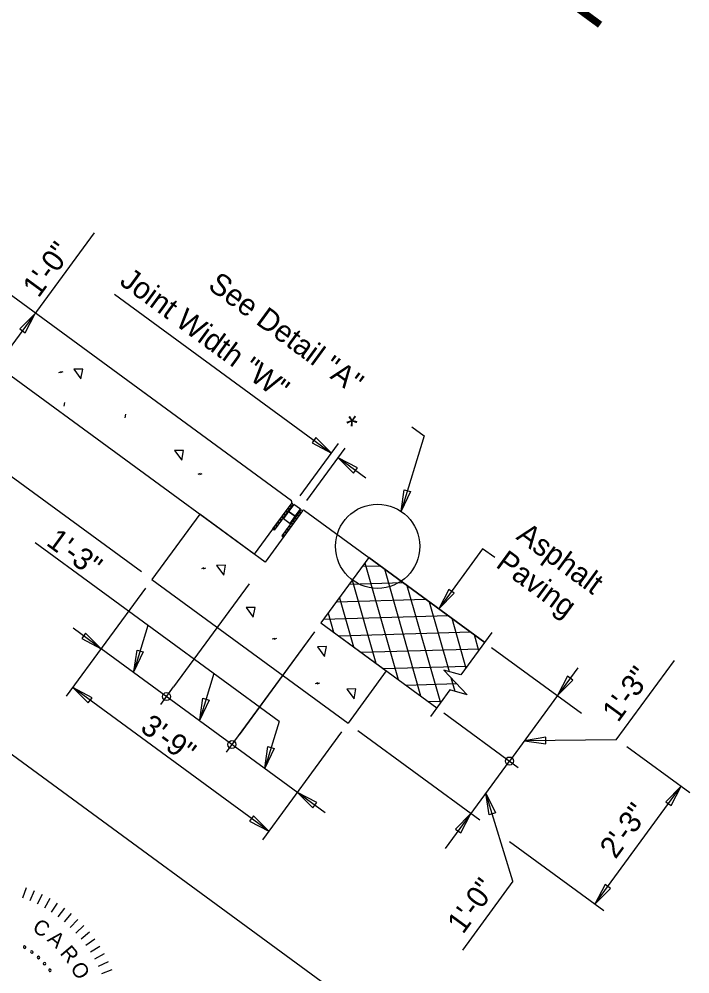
# Model space of a CAD drawing. Extents: x 1970731 to 1970899, y 796145 to 796301.
# Drawn here: x 1970821.64 to 1970837.15, y 796175.27 to 796197.36 of the extents above; entities that cross this region are included whole.
import ezdxf

# ---------------------------------------------------------------- set-up
doc = ezdxf.new("R2010")
doc.units = 0
for name, color, linetype in [('BR_AUTO DIMENSION', 7, 'Continuous'), ('BR_BORDER LINES', 7, 'Continuous'), ('BR_CONCRETE', 7, 'Continuous'), ('BR_DETAILS', 7, 'Continuous'), ('BR_STRUCTURAL STEEL', 7, 'Continuous'), ('BR_TABLE LINES', 7, 'Continuous'), ('BR_TEXT', 7, 'Continuous')]:
    doc.layers.add(name, color=color, linetype=linetype)

msp = doc.modelspace()

# ---------------------------------------------------------------- linework, layer by layer
at = {"layer": 'BR_AUTO DIMENSION'}
for p, q in [((1970818.787, 796186.151), (1970823.376, 796192.419)), ((1970823.84, 796191.001), (1970828.862, 796187.324)), ((1970824.464, 796184.573), (1970819.679, 796188.077)), ((1970830.722, 796187.929), (1970831.002, 796187.723)), ((1970831.002, 796187.723), (1970830.47, 796185.975)), ((1970828.139, 796186.336), (1970829.025, 796187.547)), ((1970828.29, 796186.225), (1970829.176, 796187.436)), ((1970829.658, 796186.74), (1970829.013, 796187.213)), ((1970827.648, 796181.116), (1970822.009, 796185.245)), ((1970832.358, 796185.11), (1970831.341, 796183.721)), ((1970832.639, 796184.904), (1970832.358, 796185.11)), ((1970824.557, 796184.195), (1970822.728, 796181.698)), ((1970826.956, 796184.298), (1970825.21, 796181.913)), ((1970823.533, 796182.797), (1970822.888, 796183.27)), ((1970824.615, 796183.337), (1970824.289, 796182.267)), ((1970828.469, 796183.19), (1970826.428, 796180.402)), ((1970828.469, 796183.19), (1970826.723, 796180.805)), ((1970828.717, 796179.001), (1970823.537, 796182.794)), ((1970832.565, 796182.826), (1970834.645, 796181.303)), ((1970834.559, 796182.358), (1970834.086, 796181.712)), ((1970835.45, 796180.686), (1970836.793, 796182.521)), ((1970826.14, 796182.221), (1970825.814, 796181.15)), ((1970827.415, 796178.576), (1970822.876, 796181.899)), ((1970824.915, 796181.51), (1970825.21, 796181.913)), ((1970834.086, 796181.712), (1970832.978, 796180.199)), ((1970831.457, 796181.313), (1970833.18, 796180.051)), ((1970827.648, 796181.116), (1970827.318, 796180.031)), ((1970829.096, 796180.873), (1970827.267, 796178.375)), ((1970829.474, 796180.906), (1970832.294, 796178.841)), ((1970835.45, 796180.686), (1970833.323, 796180.669)), ((1970835.696, 796180.533), (1970837.152, 796179.467)), ((1970831.496, 796178.174), (1970832.978, 796180.199)), ((1970834.957, 796176.891), (1970836.951, 796179.614)), ((1970833.059, 796177.422), (1970832.433, 796179.454)), ((1970832.979, 796178.34), (1970835.159, 796176.744)), ((1970833.059, 796177.422), (1970831.891, 796175.826))]:
    msp.add_line(p, q, dxfattribs=at)
for points in [[(1970821.775, 796190.106), (1970822.01, 796190.553), (1970821.654, 796190.194)], [(1970828.414, 796187.559), (1970828.862, 796187.324), (1970828.503, 796187.68)], [(1970829.461, 796186.978), (1970829.013, 796187.213), (1970829.372, 796186.857)], [(1970830.687, 796186.432), (1970830.47, 796185.975), (1970830.544, 796186.475)], [(1970831.576, 796184.169), (1970831.341, 796183.721), (1970831.697, 796184.08)], [(1970823.086, 796183.032), (1970823.533, 796182.797), (1970823.174, 796183.153)], [(1970824.506, 796182.723), (1970824.289, 796182.267), (1970824.363, 796182.767)], [(1970834.321, 796182.16), (1970834.086, 796181.712), (1970834.442, 796182.071)], [(1970823.324, 796181.664), (1970822.876, 796181.899), (1970823.235, 796181.543)], [(1970826.031, 796181.607), (1970825.814, 796181.15), (1970825.888, 796181.651)], [(1970833.822, 796180.748), (1970833.323, 796180.669), (1970833.823, 796180.598)], [(1970827.535, 796180.488), (1970827.318, 796180.031), (1970827.392, 796180.531)], [(1970828.52, 796179.239), (1970828.072, 796179.474), (1970828.431, 796179.118)], [(1970836.716, 796179.167), (1970836.951, 796179.614), (1970836.595, 796179.255)], [(1970832.509, 796178.955), (1970832.433, 796179.454), (1970832.652, 796178.999)], [(1970826.967, 796178.811), (1970827.415, 796178.576), (1970827.056, 796178.932)], [(1970831.854, 796178.535), (1970832.088, 796178.983), (1970831.732, 796178.624)], [(1970835.192, 796177.339), (1970834.957, 796176.891), (1970835.313, 796177.25)]]:
    msp.add_lwpolyline(points, close=True, dxfattribs=at)
for centre in [(1970825.046, 796181.689), (1970826.559, 796180.581), (1970832.978, 796180.199)]:
    msp.add_circle(centre, 0.0928, dxfattribs=at)
at = {"layer": 'BR_BORDER LINES'}
msp.add_line((1970811.99, 796187.287), (1970829.306, 796174.609), dxfattribs=at)
at = {"layer": 'BR_CONCRETE'}
for p, q in [((1970827.934, 796186.216), (1970803.754, 796203.919)), ((1970827.073, 796184.987), (1970802.867, 796202.709)), ((1970827.073, 796184.987), (1970802.867, 796202.709)), ((1970827.941, 796186.172), (1970827.073, 796184.987)), ((1970827.941, 796186.172), (1970827.073, 796184.987)), ((1970825.813, 796185.91), (1970824.705, 796184.397)), ((1970825.813, 796185.91), (1970824.705, 796184.397)), ((1970827.325, 796184.802), (1970825.813, 796185.91)), ((1970827.325, 796184.802), (1970825.813, 796185.91)), ((1970828.193, 796185.987), (1970827.325, 796184.802)), ((1970828.193, 796185.987), (1970827.325, 796184.802)), ((1970828.237, 796185.994), (1970829.724, 796184.905)), ((1970828.237, 796185.994), (1970829.724, 796184.905)), ((1970829.724, 796184.905), (1970828.617, 796183.392)), ((1970829.724, 796184.905), (1970828.617, 796183.392)), ((1970829.724, 796184.905), (1970828.617, 796183.392)), ((1970829.724, 796184.905), (1970828.617, 796183.392)), ((1970829.724, 796184.905), (1970832.405, 796182.942)), ((1970829.724, 796184.905), (1970832.405, 796182.942)), ((1970824.705, 796184.397), (1970829.244, 796181.074)), ((1970824.705, 796184.397), (1970829.244, 796181.074)), ((1970828.617, 796183.392), (1970830.13, 796182.285)), ((1970828.617, 796183.392), (1970830.13, 796182.285)), ((1970828.617, 796183.392), (1970830.13, 796182.285)), ((1970830.13, 796182.285), (1970829.244, 796181.074)), ((1970830.13, 796182.285), (1970829.244, 796181.074))]:
    msp.add_line(p, q, dxfattribs=at)
for centre, radius, start, end in [((1970827.916, 796186.191), 0.0313, 323.7906, 53.7906), ((1970828.218, 796185.969), 0.0312, 53.7906, 143.7906)]:
    msp.add_arc(centre, radius, start, end, dxfattribs=at)
at = {"layer": 'BR_DETAILS'}
for p, q in [((1970822.606, 796189.203), (1970822.55, 796189.182)), ((1970822.644, 796189.199), (1970822.588, 796189.178)), ((1970822.676, 796188.41), (1970822.694, 796188.491)), ((1970824.089, 796188.141), (1970824.106, 796188.221)), ((1970825.824, 796186.847), (1970825.768, 796186.826)), ((1970825.862, 796186.843), (1970825.806, 796186.822)), ((1970825.91, 796184.664), (1970825.854, 796184.644)), ((1970825.949, 796184.66), (1970825.892, 796184.639)), ((1970827.549, 796183.035), (1970827.492, 796183.014)), ((1970827.587, 796183.031), (1970827.531, 796183.01)), ((1970832.572, 796183.171), (1970831.856, 796182.193)), ((1970828.544, 796182.004), (1970828.487, 796181.984)), ((1970828.582, 796182), (1970828.525, 796181.979)), ((1970831.6, 796181.842), (1970831.15, 796181.228))]:
    msp.add_line(p, q, dxfattribs=at)
for points in [[(1970823.065, 796189.04), (1970823.107, 796189.266), (1970822.899, 796189.264), (1970823.065, 796189.04)], [(1970825.397, 796187.156), (1970825.439, 796187.383), (1970825.231, 796187.381), (1970825.397, 796187.156)], [(1970826.369, 796184.501), (1970826.412, 796184.728), (1970826.204, 796184.725), (1970826.369, 796184.501)], [(1970827.053, 796183.523), (1970827.095, 796183.75), (1970826.887, 796183.747), (1970827.053, 796183.523)], [(1970828.701, 796182.618), (1970828.743, 796182.845), (1970828.535, 796182.842), (1970828.701, 796182.618)], [(1970831.856, 796182.193), (1970831.459, 796182.304), (1970831.997, 796181.731), (1970831.6, 796181.842)], [(1970829.384, 796181.64), (1970829.427, 796181.867), (1970829.219, 796181.864), (1970829.384, 796181.64)]]:
    msp.add_lwpolyline(points, dxfattribs=at)
msp.add_circle((1970829.928, 796185.166), 0.974, dxfattribs=at)
at = {"layer": 'BR_STRUCTURAL STEEL'}
for p, q in [((1970827.95, 796186.105), (1970827.884, 796186.095)), ((1970827.799, 796185.899), (1970827.733, 796185.889)), ((1970827.809, 796185.912), (1970827.743, 796185.902)), ((1970827.846, 796185.963), (1970827.78, 796185.953)), ((1970827.856, 796185.976), (1970827.79, 796185.966)), ((1970827.893, 796186.027), (1970827.828, 796186.017)), ((1970827.903, 796186.041), (1970827.837, 796186.031)), ((1970827.94, 796186.092), (1970827.875, 796186.081)), ((1970828.117, 796185.884), (1970828.052, 796185.874)), ((1970828.154, 796185.935), (1970828.089, 796185.925)), ((1970828.164, 796185.948), (1970828.099, 796185.938)), ((1970827.62, 796185.655), (1970827.555, 796185.645)), ((1970827.658, 796185.706), (1970827.592, 796185.696)), ((1970827.667, 796185.719), (1970827.602, 796185.709)), ((1970827.705, 796185.77), (1970827.639, 796185.76)), ((1970827.714, 796185.783), (1970827.649, 796185.773)), ((1970827.752, 796185.834), (1970827.686, 796185.824)), ((1970827.762, 796185.848), (1970827.696, 796185.838)), ((1970827.966, 796185.677), (1970827.901, 796185.667)), ((1970827.976, 796185.691), (1970827.91, 796185.681)), ((1970828.013, 796185.742), (1970827.948, 796185.732)), ((1970828.023, 796185.755), (1970827.957, 796185.745)), ((1970828.06, 796185.806), (1970827.995, 796185.796)), ((1970828.07, 796185.819), (1970828.005, 796185.809)), ((1970828.107, 796185.87), (1970828.042, 796185.86)), ((1970827.563, 796185.577), (1970827.498, 796185.567)), ((1970827.573, 796185.59), (1970827.508, 796185.58)), ((1970827.611, 796185.641), (1970827.545, 796185.631)), ((1970827.788, 796185.434), (1970827.722, 796185.423)), ((1970827.825, 796185.484), (1970827.759, 796185.474)), ((1970827.835, 796185.498), (1970827.769, 796185.488)), ((1970827.872, 796185.549), (1970827.806, 796185.539)), ((1970827.882, 796185.562), (1970827.816, 796185.552)), ((1970827.919, 796185.613), (1970827.853, 796185.603)), ((1970827.929, 796185.626), (1970827.863, 796185.616)), ((1970827.778, 796185.42), (1970827.712, 796185.41))]:
    msp.add_line(p, q, dxfattribs=at)
for points in [[(1970827.954, 796186.163), (1970827.941, 796186.172), (1970827.498, 796185.567)], [(1970827.96, 796186.119), (1970827.536, 796185.539), (1970827.498, 796185.567)], [(1970828.137, 796185.99), (1970827.712, 796185.41), (1970827.75, 796185.382)], [(1970828.18, 796185.997), (1970828.193, 796185.987), (1970827.75, 796185.382)]]:
    msp.add_lwpolyline(points, dxfattribs=at)
for centre, radius, start, end in [((1970827.935, 796186.138), 0.0313, 323.7906, 53.7906), ((1970828.162, 796185.971), 0.0312, 53.7906, 143.7906)]:
    msp.add_arc(centre, radius, start, end, dxfattribs=at)
at = {"layer": 'BR_TABLE LINES'}
for p, q in [((1970829.635, 796184.783), (1970830.404, 796182.083)), ((1970829.993, 796184.709), (1970829.572, 796184.696)), ((1970830.086, 796184.641), (1970830.923, 796181.704)), ((1970829.339, 796184.379), (1970829.886, 796182.463)), ((1970830.528, 796184.317), (1970829.267, 796184.28)), ((1970830.604, 796184.261), (1970831.38, 796181.542)), ((1970831.047, 796183.937), (1970828.972, 796183.877)), ((1970829.044, 796183.976), (1970829.367, 796182.843)), ((1970831.123, 796183.881), (1970831.583, 796182.269)), ((1970831.382, 796183.691), (1970831.384, 796183.685)), ((1970831.565, 796183.557), (1970828.676, 796183.473)), ((1970828.784, 796183.62), (1970828.91, 796183.178)), ((1970831.642, 796183.501), (1970831.97, 796182.349)), ((1970832.084, 796183.178), (1970829.031, 796183.089)), ((1970832.16, 796183.122), (1970832.266, 796182.752)), ((1970832.293, 796182.789), (1970829.55, 796182.709)), ((1970831.997, 796182.385), (1970830.069, 796182.329)), ((1970831.622, 796182.13), (1970831.713, 796181.811)), ((1970831.76, 796181.984), (1970830.587, 796181.949)), ((1970831.407, 796181.578), (1970831.106, 796181.57))]:
    msp.add_line(p, q, dxfattribs=at)
for points in [[(1970828.142, 796186.024), (1970827.991, 796186.135), (1970827.871, 796185.971), (1970828.022, 796185.86)], [(1970828.022, 796185.86), (1970827.871, 796185.971), (1970827.751, 796185.807), (1970827.902, 796185.696)]]:
    msp.add_lwpolyline(points, close=True, dxfattribs=at)
msp.add_lwpolyline([(1970832.405, 796182.942), (1970829.724, 796184.905), (1970828.617, 796183.392), (1970831.297, 796181.43)], dxfattribs=at)
at = {"layer": 'BR_TEXT'}
for p, q in [((1970821.797, 796177.268), (1970821.713, 796177.028)), ((1970821.985, 796177.196), (1970821.887, 796176.961)), ((1970822.169, 796177.112), (1970822.056, 796176.884)), ((1970822.347, 796177.017), (1970822.221, 796176.796)), ((1970822.519, 796176.912), (1970822.38, 796176.699)), ((1970822.685, 796176.796), (1970822.533, 796176.592)), ((1970822.843, 796176.67), (1970822.678, 796176.476)), ((1970822.993, 796176.535), (1970822.817, 796176.351)), ((1970823.134, 796176.391), (1970822.948, 796176.218)), ((1970823.267, 796176.239), (1970823.07, 796176.077)), ((1970823.39, 796176.079), (1970823.183, 796175.929)), ((1970823.503, 796175.911), (1970823.288, 796175.775)), ((1970823.606, 796175.737), (1970823.382, 796175.614)), ((1970823.697, 796175.557), (1970823.467, 796175.448)), ((1970823.778, 796175.372), (1970823.542, 796175.277))]:
    msp.add_line(p, q, dxfattribs=at)
for centre, start, end in [((1970821.765, 796175.893), 148.8559, 328.8559), ((1970821.765, 796175.893), 328.8559, 148.8559), ((1970821.93, 796175.781), 143.3174, 323.3174), ((1970821.93, 796175.781), 323.3174, 143.3174), ((1970822.084, 796175.654), 137.779, 317.779), ((1970822.084, 796175.654), 317.779, 137.779), ((1970822.224, 796175.513), 132.2405, 312.2405), ((1970822.224, 796175.513), 312.2405, 132.2405), ((1970822.351, 796175.359), 126.702, 306.702), ((1970822.351, 796175.359), 306.702, 126.702)]:
    msp.add_arc(centre, 0.028, start, end, dxfattribs=at)

# ---------------------------------------------------------------- texts
at = {"layer": 'BR_AUTO DIMENSION'}
for s, rotation, p in [('1\'-0"', 53.7906, (1970822.084, 796190.895)), ('Joint Width "W"', 323.7906, (1970823.934, 796191.241)), ('1\'-3"', 323.7906, (1970822.239, 796185.211)), ('1\'-3"', 53.7906, (1970835.489, 796181.072)), ('3\'-9"', 323.7906, (1970824.41, 796180.912)), ('2\'-3"', 53.7906, (1970835.432, 796177.913)), ('1\'-0"', 53.7906, (1970831.903, 796176.175))]:
    msp.add_text(s, height=0.5, rotation=rotation, dxfattribs=at).set_placement(p)
at = {"layer": 'BR_TEXT'}
for s, height, rotation, p in [('DEFLECTION JOINT DETAIL', 1.5, 323.7906, (1970813.588, 796212.86)), ('See Detail "A"', 0.49995, 323.7906, (1970825.977, 796191.141)), ('*', 0.5, 323.7906, (1970829.014, 796187.851)), ('Asphalt ', 0.4999, 323.7906, (1970833.111, 796185.349)), ('Paving', 0.4999, 323.7906, (1970832.638, 796184.704)), ('C', 0.349, 328.5187, (1970821.919, 796176.278)), ('A', 0.349, 319.4887, (1970822.268, 796176.047)), ('R', 0.349, 310.4587, (1970822.564, 796175.746)), ('INFRASTRUCTURE', 0.29909, 323.3174, (1970819.852, 796175.586)), ('O', 0.349, 301.4286, (1970822.809, 796175.419))]:
    msp.add_text(s, height=height, rotation=rotation, dxfattribs=at).set_placement(p)

doc.saveas('drawing.dxf')
